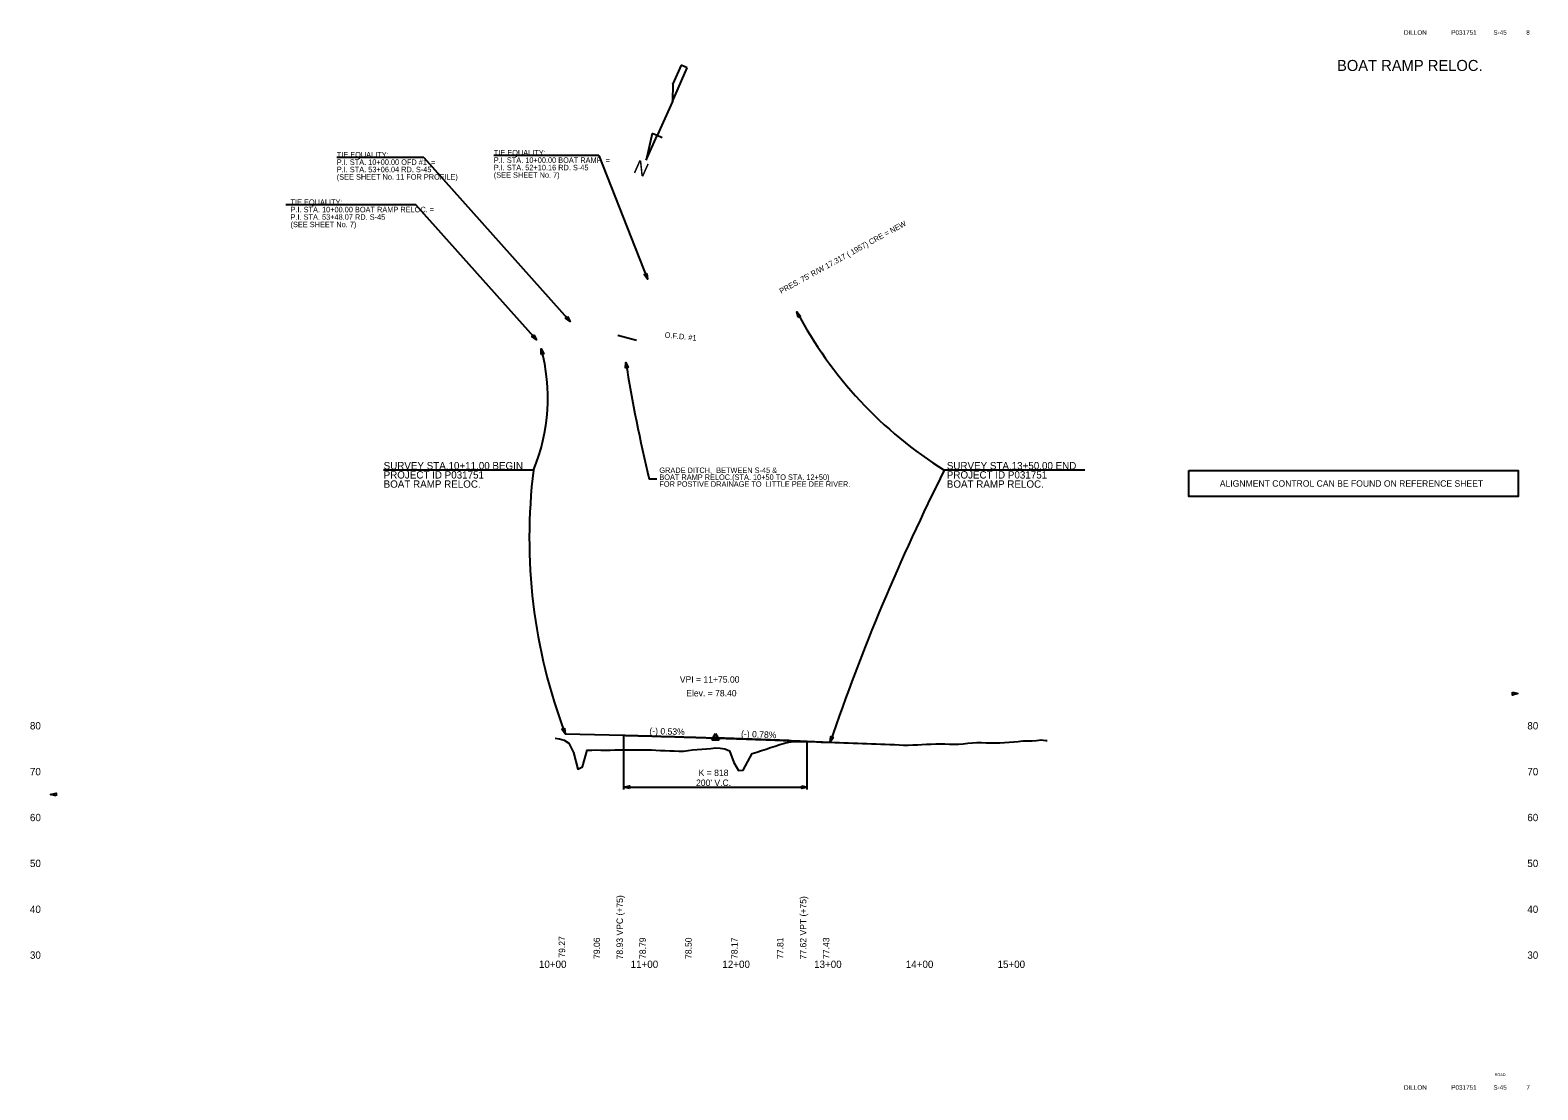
# Model space of a CAD drawing. Extents: x -3336 to 3318, y -3606 to 6276.
# Drawn here: x -72 to 1571, y 1658 to 2813 of the extents above; entities that cross this region are included whole.
import ezdxf

# ---------------------------------------------------------------- set-up
doc = ezdxf.new("R2010")
doc.units = 0
for name, color, linetype in [('RD_DDB_ElevTX', 7, 'Continuous'), ('RD_DDB_GradeTX', 7, 'Continuous'), ('RD_DDB_Profile_EX', 7, 'Continuous'), ('RD_DDB_Profile_Lbl', 7, 'Continuous'), ('RD_DDB_Profile_PR', 7, 'Continuous'), ('RD_DDB_StaTX', 7, 'Continuous'), ('RD_DDB_StripGrade', 7, 'Continuous'), ('RD_DDB_VCLbl', 7, 'Continuous'), ('RD_EX_Misc', 7, 'Continuous'), ('RD_EX_RW_TX', 7, 'Continuous'), ('RD_HC_Data', 7, 'Continuous'), ('RD_PD_Final_TX', 7, 'Continuous'), ('RD_SHT_TX', 7, 'Continuous'), ('RD_Sketch1', 7, 'Continuous'), ('RD_TX_Drainage', 7, 'Continuous'), ('RD_TX_RoadID', 7, 'Continuous'), ('RD_XS_NPDES', 7, 'Continuous')]:
    doc.layers.add(name, color=color, linetype=linetype)

msp = doc.modelspace()

# ---------------------------------------------------------------- linework, layer by layer
at = {"layer": 'RD_DDB_GradeTX'}
for p in [(595, 2044.1), (754.9, 2038.9)]:
    msp.add_line(p, (675, 2042), dxfattribs=at)
at = {"layer": 'RD_DDB_Profile_EX'}
for points in [[(500, 2041.5), (505, 2040.6), (510, 2039.3), (515, 2036.1), (520, 2025.9), (525, 2007.8), (530, 2010.1), (535, 2028.5), (540, 2028.5), (545, 2028.6), (550, 2028.5), (555, 2028.5), (560, 2028.5), (565, 2028.6), (570, 2028.7), (575, 2028.8), (580, 2028.8), (585, 2028.9), (590, 2028.9), (595, 2028.9), (600, 2028.8), (605, 2028.6), (610, 2028.4), (615, 2028.1), (620, 2027.9), (625, 2027.7), (630, 2027.5), (635, 2027.3), (640, 2027.3), (645, 2028.1), (650, 2028.6), (655, 2029.1), (660, 2029.5), (665, 2030), (670, 2030.4), (675, 2030.9), (680, 2030.5), (685, 2029.8), (690, 2027.8), (695, 2015.1), (700, 2006.3), (705, 2006.6), (710, 2016.2), (715, 2024.9), (720, 2026.4), (725, 2028), (730, 2029.6), (735, 2031.2), (740, 2032.8), (745, 2034.4), (750, 2035.9), (755, 2037.2), (760, 2037.7), (765, 2037.7), (770, 2037.7), (775, 2037.7), (780, 2037.7), (785, 2037.5), (790, 2037.3), (795, 2037), (800, 2037), (805, 2036.9), (810, 2036.8), (815, 2036.5), (820, 2036.3), (825, 2036.1), (830, 2035.9), (835, 2035.8), (840, 2035.6), (845, 2035.4), (850, 2035.2), (855, 2035), (860, 2034.8), (865, 2034.7), (870, 2034.5), (875, 2034.2), (880, 2034), (885, 2034), (890, 2034.1), (895, 2034.3), (900, 2034.6), (905, 2034.8), (910, 2035.1), (915, 2035.3), (920, 2035.2), (925, 2035.2), (930, 2035), (935, 2034.9), (940, 2035), (945, 2035.4), (950, 2036), (955, 2036.5), (960, 2036.6), (965, 2036.6), (970, 2036.5), (975, 2036.5), (980, 2036.5), (985, 2036.5), (990, 2036.6), (995, 2037.1), (1000, 2037.6)], [(1000, 2037.6), (1005, 2037.9), (1010, 2038.4), (1015, 2038.6), (1020, 2038.6), (1025, 2038.9), (1030, 2039.6), (1035, 2039.1), (1036.6, 2038.9)]]:
    msp.add_lwpolyline(points, dxfattribs=at)
at = {"layer": 'RD_DDB_Profile_PR'}
for p, q in [((511, 2046.3), (575, 2044.6)), ((775, 2038.1), (800, 2037.1))]:
    msp.add_line(p, q, dxfattribs=at)
msp.add_spline([(575, 2044.6), (579, 2044.5), (583, 2044.4), (587, 2044.3), (591, 2044.2), (595, 2044.1), (599, 2044), (603, 2043.9), (607, 2043.8), (611, 2043.7), (615, 2043.5), (619, 2043.4), (623, 2043.3), (627, 2043.2), (631, 2043.1), (635, 2042.9), (639, 2042.8), (643, 2042.7), (647, 2042.6), (651, 2042.5), (655, 2042.3), (659, 2042.2), (663, 2042.1), (667, 2041.9), (671, 2041.8), (675, 2041.7), (679, 2041.6), (683, 2041.4), (687, 2041.3), (691, 2041.2), (695, 2041), (699, 2040.9), (703, 2040.7), (707, 2040.6), (711, 2040.5), (715, 2040.3), (719, 2040.2), (723, 2040), (727, 2039.9), (731, 2039.8), (735, 2039.6), (739, 2039.5), (743, 2039.3), (747, 2039.2), (751, 2039), (755, 2038.9), (759, 2038.7), (763, 2038.6), (767, 2038.4), (771, 2038.3), (775, 2038.1)], degree=3, dxfattribs=at)
at = {"layer": 'RD_DDB_VCLbl'}
for p, q in [((575, 1985.6), (575, 2044.6)), ((775, 1985.6), (775, 2038.1)), ((575, 1988.1), (775, 1988.1))]:
    msp.add_line(p, q, dxfattribs=at)
at = {"layer": 'RD_EX_Misc'}
for p, q in [((627.9, 2735.5), (644.2, 2772.2)), ((637.5, 2775.1), (628.4, 2754.8)), ((644.2, 2772.2), (637.5, 2775.1)), ((628.5, 2755), (627.9, 2735.5)), ((628.4, 2754.8), (628.5, 2755)), ((627.9, 2735.5), (611.3, 2698.3)), ((606, 2700.7), (599.4, 2671.4)), ((599.4, 2671.4), (611.3, 2698.3)), ((606, 2700.7), (605.8, 2700.3)), ((611.3, 2698.3), (606, 2700.7)), ((616.7, 2695.9), (611.3, 2698.3)), ((599.4, 2671.4), (599.4, 2671.4))]:
    msp.add_line(p, q, dxfattribs=at)
at = {"layer": 'RD_HC_Data'}
for p, q in [((356.8, 2674.5), (262, 2674.5)), ((356.8, 2674.5), (516.5, 2495.8)), ((547.8, 2676.7), (433.2, 2676.7)), ((547.8, 2676.7), (600.7, 2541.8)), ((348.2, 2622.8), (206.6, 2622.8)), ((479.6, 2475.7), (348.2, 2622.8)), ((671, 2039.7), (675, 2046.6)), ((671, 2039.7), (679, 2039.7)), ((675, 2046.6), (679, 2039.7))]:
    msp.add_line(p, q, dxfattribs=at)
msp.add_circle((675, 2042), 0.529, dxfattribs=at)
at = {"layer": 'RD_PD_Final_TX'}
for p, q in [((476.4, 2333.5), (313.1, 2333.5)), ((611, 2323.7), (602.6, 2323.7)), ((1077.5, 2333.5), (924.3, 2333.5))]:
    msp.add_line(p, q, dxfattribs=at)
for centre, radius, start, end in [((1164.4, 2717.9), 453.2, 207.83, 238.0019), ((287.1, 2412.2), 205, 337.423, 15.2258), ((2353.6, 2738.9), 1799.6, 189.2026, 193.3392), ((1073, 2259.8), 601.1, 172.9542, 200.7945), ((2988.5, 1293.7), 2311.3, 153.2642, 161.2367)]:
    msp.add_arc(centre, radius, start, end, dxfattribs=at)
at = {"layer": 'RD_Sketch1'}
msp.add_lwpolyline([(1190.8, 2333.3), (1550, 2333.3), (1550, 2304.9), (1190.8, 2304.9)], close=True, dxfattribs=at)
at = {"layer": 'RD_TX_Drainage'}
for points in [[(599.9, 2547.9), (600.7, 2541.8), (597.1, 2546.8)], [(513.6, 2501.3), (516.5, 2495.8), (511.4, 2499.3)], [(765, 2500.2), (763.6, 2506.3), (767.7, 2501.6)], [(476.7, 2481.2), (479.6, 2475.7), (474.5, 2479.2)], [(485, 2459.8), (484.9, 2466), (487.9, 2460.6)], [(576.7, 2444.9), (577.2, 2451.1), (579.7, 2445.4)], [(1543.8, 2091.5), (1549.8, 2090), (1543.8, 2088.5)], [(510.2, 2052.5), (511, 2046.3), (507.4, 2051.4)], [(803.4, 2042.3), (800, 2037.1), (800.5, 2043.3)], [(581, 1986.6), (575, 1988.1), (581, 1989.6)], [(769, 1989.6), (775, 1988.1), (769, 1986.6)], [(-44, 1978.5), (-50, 1980), (-44, 1981.5)]]:
    msp.add_lwpolyline(points, close=True, dxfattribs=at)
at = {"layer": 'RD_XS_NPDES'}
msp.add_line((568.3, 2480.8), (588.8, 2475.5), dxfattribs=at)

# ---------------------------------------------------------------- texts
at = {"layer": 'RD_DDB_ElevTX'}
for s, p in [('80', (-72.5, 2051)), ('80', (1560, 2051)), ('70', (-72.5, 2001)), ('70', (1560, 2001)), ('60', (-72.5, 1951)), ('60', (1560, 1951)), ('50', (-72.5, 1901)), ('50', (1560, 1901)), ('40', (-72.5, 1851)), ('40', (1560, 1851)), ('30', (-72.5, 1801)), ('30', (1560, 1801))]:
    msp.add_text(s, height=8, dxfattribs=at).set_placement(p)
at = {"layer": 'RD_DDB_GradeTX'}
for s, rotation, p in [('(-) 0.53%', 358.4775, (602.8, 2045.9)), ('(-) 0.78%', 357.7777, (702.7, 2042.9))]:
    msp.add_text(s, height=7, rotation=rotation, dxfattribs=at).set_placement(p)
at = {"layer": 'RD_DDB_Profile_Lbl'}
for s, p in [('VPI = 11+75.00', (636, 2102)), ('Elev. = 78.40', (643, 2087))]:
    msp.add_text(s, height=7, dxfattribs=at).set_placement(p)
msp.add_text('79.27', height=7, rotation=90, dxfattribs=at).set_placement((511, 1802.2))
at = {"layer": 'RD_DDB_StaTX'}
for s, p in [('10+00', (482.4, 1791)), ('11+00', (582.4, 1791)), ('12+00', (682.4, 1791)), ('13+00', (782.4, 1791)), ('14+00', (882.4, 1791)), ('15+00', (982.4, 1791))]:
    msp.add_text(s, height=8, dxfattribs=at).set_placement(p)
at = {"layer": 'RD_DDB_StripGrade'}
for s, p in [('78.93 VPC (+75)', (574, 1800.3)), ('77.62 VPT (+75)', (774, 1800.3)), ('79.06', (549, 1800.8)), ('78.79', (599, 1800.8)), ('78.50', (649, 1800.8)), ('78.17', (699, 1800.8)), ('77.81', (749, 1800.8)), ('77.43', (799, 1800.8))]:
    msp.add_text(s, height=7, rotation=90, dxfattribs=at).set_placement(p)
at = {"layer": 'RD_DDB_VCLbl'}
for s, p in [('K = 818', (656.5, 2000.2)), ("200' V.C.", (653.7, 1989.4))]:
    msp.add_text(s, height=7, dxfattribs=at).set_placement(p)
at = {"layer": 'RD_EX_Misc'}
msp.add_text('N', height=15, rotation=156.0325, dxfattribs=at).set_placement((603.7, 2666.5))
at = {"layer": 'RD_EX_RW_TX'}
msp.add_text("PRES. 75' R/W 17.317 ( 1957) CRE = NEW", height=6, rotation=28.7137, dxfattribs=at).set_placement((746.6, 2525.7))
at = {"layer": 'RD_HC_Data'}
for s, p in [('TIE EQUALITY:', (262, 2674.5)), ('TIE EQUALITY:', (433.2, 2676.7)), ('P.I. STA. 10+00.00 OFD #1  =', (262, 2666.4)), ('P.I. STA. 53+06.04 RD. S-45', (262, 2658.4)), ('P.I. STA. 10+00.00 BOAT RAMP  =', (433.2, 2668.6)), ('P.I. STA. 52+10.16 RD. S-45', (433.2, 2660.5)), ('(SEE SHEET No. 11 FOR PROFILE)', (262, 2650.3)), ('(SEE SHEET No. 7)', (433.2, 2652.4)), ('TIE EQUALITY:', (211.6, 2622.8)), ('P.I. STA. 10+00.00 BOAT RAMP RELOC. =', (211.6, 2614.7)), ('(SEE SHEET No. 7)', (211.6, 2598.5)), ('P.I. STA. 53+48.07 RD. S-45', (211.6, 2606.6))]:
    msp.add_text(s, height=6, dxfattribs=at).set_placement(p)
at = {"layer": 'RD_PD_Final_TX'}
for s, height, p in [('SURVEY STA.10+11.00 BEGIN', 8, (313.1, 2334.5)), ('GRADE DITCH,  BETWEEN S-45 &', 6, (613.7, 2330.5)), ('SURVEY STA.13+50.00 END', 8, (927.1, 2334.5)), ('PROJECT ID P031751', 8, (313.1, 2324.5)), ('BOAT RAMP RELOC.', 8, (313.1, 2314.5)), ('BOAT RAMP RELOC.(STA. 10+50 TO STA. 12+50)', 6, (613.7, 2323)), ('FOR POSTIVE DRAINAGE TO  LITTLE PEE DEE RIVER.', 6, (613.7, 2315.5)), ('PROJECT ID P031751', 8, (927.1, 2324.5)), ('BOAT RAMP RELOC.', 8, (927.1, 2314.5))]:
    msp.add_text(s, height=height, dxfattribs=at).set_placement(p)
at = {"layer": 'RD_SHT_TX'}
for s, height, p in [('DILLON', 5, (1425.5, 2808.2)), ('P031751', 5, (1477.1, 2808.2)), ('S-45', 5, (1523, 2808.2)), ('8', 5, (1558.8, 2808.2)), ('BOAT RAMP RELOC.', 12, (1352.5, 2768.8)), ('DILLON', 5, (1425.5, 1658.2)), ('P031751', 5, (1477.1, 1658.2)), ('S-45', 5, (1523, 1658.2)), ('ROAD', 3, (1524.3, 1673.1)), ('7', 5, (1558.9, 1658.2))]:
    msp.add_text(s, height=height, dxfattribs=at).set_placement(p)
at = {"layer": 'RD_Sketch1'}
msp.add_text('ALIGNMENT CONTROL CAN BE FOUND ON REFERENCE SHEET', height=7, dxfattribs=at).set_placement((1224.7, 2315.6))
at = {"layer": 'RD_TX_RoadID'}
msp.add_text('O.F.D. #1', height=6, rotation=354.1355, dxfattribs=at).set_placement((619.3, 2478.2))

doc.saveas('drawing.dxf')
